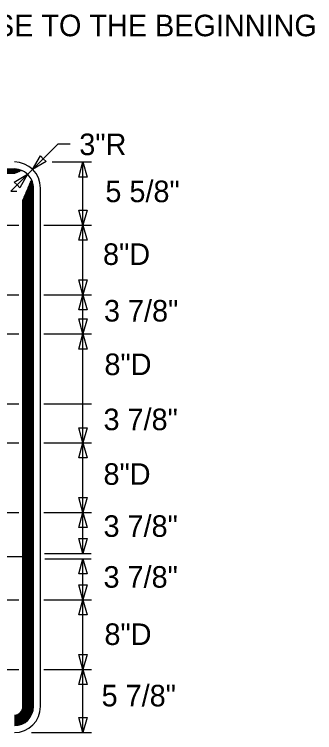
# Model space of a CAD drawing. Extents: x 15273 to 18137, y 1908 to 6555.
# Drawn here: x 17974.2 to 18091.3, y 2387.3 to 2667.1 of the extents above; entities that cross this region are included whole.
import ezdxf

# ---------------------------------------------------------------- set-up
doc = ezdxf.new("R2010")
doc.units = 0
doc.layers.add('TYPICAL_EX', color=7, linetype='Continuous')
doc.layers.add('TYPICAL_TEXT_DIMEN_PR', color=7, linetype='Continuous')

msp = doc.modelspace()

# ---------------------------------------------------------------- linework, layer by layer
at = {"layer": 'TYPICAL_EX'}
for p, q in [((17974.24, 2606.79), (17845.88, 2606.79)), ((17974.24, 2606.68), (17846.02, 2606.68)), ((17974.24, 2606.57), (17846.08, 2606.57)), ((17974.24, 2606.46), (17846.14, 2606.46)), ((17974.24, 2606.35), (17846.2, 2606.35)), ((17974.24, 2606.23), (17846.26, 2606.23)), ((17974.24, 2606.12), (17846.31, 2606.12)), ((17974.24, 2606.01), (17846.37, 2606.01)), ((17974.24, 2605.9), (17846.43, 2605.9)), ((17974.24, 2605.79), (17846.49, 2605.79)), ((17974.24, 2605.67), (17846.55, 2605.67)), ((17974.24, 2605.56), (17846.6, 2605.56)), ((17974.24, 2605.45), (17846.66, 2605.45)), ((17974.24, 2605.34), (17846.72, 2605.34)), ((17974.24, 2605.23), (17846.78, 2605.23)), ((17974.24, 2605.11), (17846.84, 2605.11)), ((17979.58, 2451.37), (17979.58, 2599.44)), ((17979.69, 2451.39), (17979.69, 2599.44)), ((17979.8, 2451.37), (17979.8, 2599.44)), ((17979.92, 2451.26), (17979.92, 2599.44)), ((17980.03, 2451.33), (17980.03, 2599.44)), ((17980.14, 2451.39), (17980.14, 2599.44)), ((17980.25, 2451.44), (17980.25, 2599.44)), ((17980.36, 2451.35), (17980.36, 2599.44)), ((17980.48, 2451.39), (17980.48, 2599.44)), ((17980.59, 2451.35), (17980.59, 2599.44)), ((17980.7, 2451.37), (17980.7, 2599.44)), ((17980.81, 2451.37), (17980.81, 2599.44)), ((17980.92, 2451.37), (17980.92, 2599.44)), ((17981.03, 2451.41), (17981.03, 2599.44)), ((17981.15, 2451.44), (17981.15, 2599.44)), ((17981.26, 2451.37), (17981.26, 2599.44)), ((17981.37, 2451.37), (17981.37, 2599.44)), ((17981.48, 2451.41), (17981.48, 2599.44)), ((17981.6, 2451.37), (17981.6, 2599.44)), ((17981.71, 2451.42), (17981.71, 2599.44)), ((17984.42, 2451.4), (17984.42, 2599.44)), ((17978.35, 2451.29), (17978.35, 2596.59)), ((17978.46, 2451.37), (17978.46, 2596.85)), ((17978.57, 2451.39), (17978.57, 2597.11)), ((17978.68, 2451.29), (17978.68, 2597.37)), ((17978.8, 2451.31), (17978.8, 2597.63)), ((17978.91, 2451.35), (17978.91, 2597.89)), ((17979.02, 2451.39), (17979.02, 2598.15)), ((17979.13, 2451.33), (17979.13, 2598.41)), ((17979.24, 2451.35), (17979.24, 2598.67)), ((17979.35, 2451.33), (17979.35, 2598.93)), ((17979.47, 2451.22), (17979.47, 2599.19)), ((17977.6, 2451.35), (17977.6, 2594.86)), ((17977.67, 2451.35), (17977.67, 2595.03)), ((17977.79, 2451.45), (17977.79, 2595.29)), ((17977.9, 2451.43), (17977.9, 2595.55)), ((17978.01, 2451.35), (17978.01, 2595.81)), ((17978.12, 2451.35), (17978.12, 2596.07)), ((17978.24, 2451.44), (17978.24, 2596.33)), ((17828.79, 2455.92), (17977.54, 2455.92)), ((17977.6, 2397.51), (17977.6, 2451.35)), ((17977.67, 2397.51), (17977.67, 2451.35)), ((17977.78, 2397.51), (17977.78, 2451.35)), ((17977.9, 2397.51), (17977.9, 2451.35)), ((17978.01, 2397.51), (17978.01, 2451.35)), ((17978.12, 2397.51), (17978.12, 2451.35)), ((17978.23, 2397.51), (17978.23, 2451.35)), ((17978.35, 2397.51), (17978.35, 2451.35)), ((17978.46, 2397.51), (17978.46, 2451.35)), ((17978.57, 2397.51), (17978.57, 2451.35)), ((17978.68, 2397.51), (17978.68, 2451.35)), ((17978.79, 2397.51), (17978.79, 2451.35)), ((17978.91, 2397.51), (17978.91, 2451.35)), ((17979.02, 2397.51), (17979.02, 2451.35)), ((17979.13, 2397.51), (17979.13, 2451.35)), ((17979.24, 2397.51), (17979.24, 2451.35)), ((17979.35, 2397.51), (17979.35, 2451.35)), ((17979.47, 2397.51), (17979.47, 2451.35)), ((17979.58, 2397.51), (17979.58, 2451.35)), ((17979.69, 2397.51), (17979.69, 2451.35)), ((17979.8, 2397.51), (17979.8, 2451.35)), ((17979.92, 2397.51), (17979.92, 2451.35)), ((17980.03, 2397.51), (17980.03, 2451.35)), ((17980.14, 2397.51), (17980.14, 2451.35)), ((17980.25, 2397.51), (17980.25, 2451.35)), ((17980.36, 2397.51), (17980.36, 2451.35)), ((17980.48, 2397.51), (17980.48, 2451.35)), ((17980.59, 2397.51), (17980.59, 2451.35)), ((17980.7, 2397.51), (17980.7, 2451.35)), ((17980.81, 2397.51), (17980.81, 2451.35)), ((17980.92, 2397.51), (17980.92, 2451.35)), ((17981.03, 2397.51), (17981.03, 2451.35)), ((17981.15, 2397.51), (17981.15, 2451.35)), ((17981.26, 2397.51), (17981.26, 2451.35)), ((17981.37, 2397.51), (17981.37, 2451.35)), ((17981.48, 2397.51), (17981.48, 2451.35)), ((17981.6, 2397.51), (17981.6, 2451.35)), ((17981.71, 2397.51), (17981.71, 2451.35)), ((17984.42, 2397.51), (17984.42, 2451.35))]:
    msp.add_line(p, q, dxfattribs=at)
for centre, radius, start, end in [((17974.24, 2599.44), 10.18, 0, 90), ((17974.24, 2599.44), 7.46, 39.0673, 90), ((17974.24, 2599.44), 7.35, 66.9087, 90), ((17974.24, 2599.44), 7.24, 67.8069, 90), ((17974.24, 2599.44), 7.13, 68.7489, 90), ((17974.24, 2599.44), 7.02, 69.7388, 90), ((17974.24, 2599.44), 6.9, 70.7811, 90), ((17974.24, 2599.44), 6.79, 71.8812, 90), ((17974.24, 2599.44), 6.68, 73.0455, 90), ((17974.24, 2599.44), 6.57, 74.2814, 90), ((17974.24, 2599.44), 6.46, 75.5979, 90), ((17974.24, 2599.44), 6.34, 77.006, 90), ((17974.24, 2599.44), 6.23, 78.5194, 90), ((17974.24, 2599.44), 6.12, 80.1555, 90), ((17974.24, 2599.44), 6.01, 81.9371, 90), ((17974.24, 2599.44), 5.9, 83.8949, 90), ((17974.24, 2599.44), 5.78, 86.0727, 90), ((17974.24, 2599.44), 5.67, 88.5362, 90), ((17974.24, 2599.44), 7.46, 0, 39.0664), ((17974.24, 2599.44), 7.02, 0, 22.4279), ((17974.24, 2599.44), 7.13, 0, 23.2988), ((17974.24, 2599.44), 7.24, 0, 24.1309), ((17974.24, 2599.44), 7.35, 0, 24.1308), ((17974.24, 2599.44), 5.34, 0, 0.1031), ((17974.24, 2599.44), 5.45, 0, 2.6891), ((17974.24, 2599.44), 5.56, 0, 4.9634), ((17974.24, 2599.44), 5.67, 0, 6.9999), ((17974.24, 2599.44), 5.78, 0, 8.847), ((17974.24, 2599.44), 5.9, 0, 10.5386), ((17974.24, 2599.44), 6.01, 0, 12.0996), ((17974.24, 2599.44), 6.12, 0, 13.5489), ((17974.24, 2599.44), 6.23, 0, 14.9011), ((17974.24, 2599.44), 6.34, 0, 16.1683), ((17974.24, 2599.44), 6.46, 0, 17.36), ((17974.24, 2599.44), 6.57, 0, 18.4842), ((17974.24, 2599.44), 6.68, 0, 19.5478), ((17974.24, 2599.44), 6.79, 0, 20.5564), ((17974.24, 2599.44), 6.9, 0, 21.5151), ((17974.24, 2397.51), 7.46, 270, 0), ((17974.24, 2397.51), 3.36, 270, 0), ((17974.24, 2397.51), 7.35, 270, 0), ((17974.24, 2397.51), 7.24, 270, 0), ((17974.24, 2397.51), 7.13, 270, 0), ((17974.24, 2397.51), 7.02, 270, 0), ((17974.24, 2397.51), 6.9, 270, 0), ((17974.24, 2397.51), 6.79, 270, 0), ((17974.24, 2397.51), 6.68, 270, 0), ((17974.24, 2397.51), 6.57, 270, 0), ((17974.24, 2397.51), 6.46, 270, 0), ((17974.24, 2397.51), 6.34, 270, 0), ((17974.24, 2397.51), 6.23, 270, 0), ((17974.24, 2397.51), 6.12, 270, 0), ((17974.24, 2397.51), 6.01, 270, 0), ((17974.24, 2397.51), 5.9, 270, 0), ((17974.24, 2397.51), 5.78, 270, 0), ((17974.24, 2397.51), 5.67, 270, 0), ((17974.24, 2397.51), 5.56, 270, 0), ((17974.24, 2397.51), 5.45, 270, 0), ((17974.24, 2397.51), 5.34, 270, 0), ((17974.24, 2397.51), 5.22, 270, 0), ((17974.24, 2397.51), 5.11, 270, 0), ((17974.24, 2397.51), 5, 270, 0), ((17974.24, 2397.51), 4.89, 270, 0), ((17974.24, 2397.51), 4.78, 270, 0), ((17974.24, 2397.51), 4.66, 270, 0), ((17974.24, 2397.51), 4.55, 270, 0), ((17974.24, 2397.51), 4.44, 270, 0), ((17974.24, 2397.51), 4.33, 270, 0), ((17974.24, 2397.51), 4.21, 270, 0), ((17974.24, 2397.51), 4.1, 270, 0), ((17974.24, 2397.51), 3.99, 270, 0), ((17974.24, 2397.51), 3.88, 270, 0), ((17974.24, 2397.51), 3.77, 270, 0), ((17974.24, 2397.51), 3.65, 270, 0), ((17974.24, 2397.51), 3.54, 270, 0), ((17974.24, 2397.51), 3.43, 270, 0), ((17974.24, 2397.51), 10.18, 270, 0)]:
    msp.add_arc(centre, radius, start, end, dxfattribs=at)
at = {"layer": 'TYPICAL_TEXT_DIMEN_PR'}
for p, q in [((17981.35, 2606.73), (17991.31, 2616.68)), ((17991.31, 2616.68), (17996.01, 2616.68)), ((17981.35, 2606.73), (17984.39, 2611.98)), ((17984.39, 2611.98), (17985.5, 2610.87)), ((17985.5, 2610.87), (17986.61, 2609.76)), ((17986.61, 2609.76), (17981.35, 2606.73)), ((17988.95, 2609.62), (18004.31, 2609.62)), ((17999.42, 2603.76), (18000.99, 2609.62)), ((18000.99, 2585.02), (18000.99, 2609.62)), ((18000.99, 2609.62), (18002.56, 2603.76)), ((17979.44, 2604.81), (17981.32, 2606.69)), ((17972.91, 2598.28), (17979.44, 2604.81)), ((17974.18, 2601.77), (17979.43, 2604.81)), ((17979.43, 2604.81), (17976.4, 2599.55)), ((18000.99, 2603.76), (17999.42, 2603.76)), ((18002.56, 2603.76), (18000.99, 2603.76)), ((17975.29, 2600.66), (17974.18, 2601.77)), ((17976.4, 2599.55), (17975.29, 2600.66)), ((17972.91, 2598.28), (17975.15, 2598.28)), ((18000.99, 2585.02), (17999.42, 2590.88)), ((17999.42, 2590.88), (18000.99, 2590.88)), ((18000.99, 2590.88), (18002.56, 2590.88)), ((18002.56, 2590.88), (18000.99, 2585.02)), ((17951.77, 2585.02), (17975.94, 2585.02)), ((17985.79, 2585.02), (18004.31, 2585.02)), ((17999.42, 2579.16), (18000.99, 2585.02)), ((18000.99, 2557.88), (18000.99, 2585.02)), ((18000.99, 2585.02), (18002.56, 2579.16)), ((18000.99, 2579.16), (17999.42, 2579.16)), ((18002.56, 2579.16), (18000.99, 2579.16)), ((18000.99, 2557.88), (17999.42, 2563.74)), ((17999.42, 2563.74), (18000.99, 2563.74)), ((18000.99, 2563.74), (18002.56, 2563.74)), ((18002.56, 2563.74), (18000.99, 2557.88)), ((17951.77, 2557.88), (17975.94, 2557.88)), ((17985.79, 2557.88), (18004.31, 2557.88)), ((17999.42, 2552.01), (18000.99, 2557.88)), ((18000.99, 2542.61), (18000.99, 2557.88)), ((18000.99, 2557.88), (18002.56, 2552.01)), ((18000.99, 2552.01), (17999.42, 2552.01)), ((18002.56, 2552.01), (18000.99, 2552.01)), ((18000.99, 2542.61), (17999.42, 2548.47)), ((17999.42, 2548.47), (18000.99, 2548.47)), ((18000.99, 2548.47), (18002.56, 2548.47)), ((18002.56, 2548.47), (18000.99, 2542.61)), ((17940.51, 2542.61), (17975.94, 2542.61)), ((17985.79, 2542.61), (18004.31, 2542.61)), ((17999.42, 2536.75), (18000.99, 2542.61)), ((18000.99, 2515.46), (18000.99, 2542.61)), ((18000.99, 2542.61), (18002.56, 2536.75)), ((18000.99, 2536.75), (17999.42, 2536.75)), ((18002.56, 2536.75), (18000.99, 2536.75)), ((17940.51, 2515.46), (17975.94, 2515.46)), ((17985.79, 2515.46), (18004.31, 2515.46)), ((18000.99, 2500.19), (18000.99, 2515.46)), ((18000.99, 2500.19), (17999.42, 2506.05)), ((17999.42, 2506.05), (18000.99, 2506.05)), ((18000.99, 2506.05), (18002.56, 2506.05)), ((18002.56, 2506.05), (18000.99, 2500.19)), ((17950.76, 2500.19), (17975.94, 2500.19)), ((17985.79, 2500.19), (18004.31, 2500.19)), ((17999.42, 2494.33), (18000.99, 2500.19)), ((18000.99, 2473.05), (18000.99, 2500.19)), ((18000.99, 2500.19), (18002.56, 2494.33)), ((18000.99, 2494.33), (17999.42, 2494.33)), ((18002.56, 2494.33), (18000.99, 2494.33)), ((18000.99, 2473.05), (17999.42, 2478.91)), ((17999.42, 2478.91), (18000.99, 2478.91)), ((18000.99, 2478.91), (18002.56, 2478.91)), ((18002.56, 2478.91), (18000.99, 2473.05)), ((17950.76, 2473.05), (17975.94, 2473.05)), ((17985.79, 2473.05), (18004.31, 2473.05)), ((17999.42, 2467.18), (18000.99, 2473.05)), ((18000.99, 2457.07), (18000.99, 2473.05)), ((18000.99, 2473.05), (18000.99, 2473.05)), ((18000.99, 2473.05), (18000.99, 2473.04)), ((18000.99, 2473.05), (18002.56, 2467.18)), ((18000.99, 2467.18), (17999.42, 2467.18)), ((18002.56, 2467.18), (18000.99, 2467.18)), ((18000.99, 2457.07), (17999.42, 2462.93)), ((17999.42, 2462.93), (18000.99, 2462.93)), ((18000.99, 2462.93), (18002.56, 2462.93)), ((18002.56, 2462.93), (18000.99, 2457.07)), ((17986.04, 2457.07), (18004.22, 2457.07)), ((17986.13, 2455.06), (18004.13, 2455.06)), ((17999.42, 2449.19), (18000.99, 2455.05)), ((18000.99, 2439.07), (18000.99, 2455.05)), ((18000.99, 2455.05), (18002.56, 2449.19)), ((18002.2, 2451.35), (18002.21, 2451.34)), ((18000.99, 2449.19), (17999.42, 2449.19)), ((18002.56, 2449.19), (18000.99, 2449.19)), ((18000.99, 2439.07), (17999.42, 2444.94)), ((17999.42, 2444.94), (18000.99, 2444.94)), ((18000.99, 2444.94), (18002.56, 2444.94)), ((18002.56, 2444.94), (18000.99, 2439.07)), ((17956.07, 2439.07), (17975.94, 2439.07)), ((17985.79, 2439.07), (18004.31, 2439.07)), ((17999.42, 2433.21), (18000.99, 2439.07)), ((18000.99, 2411.93), (18000.99, 2439.07)), ((18000.99, 2439.07), (18002.56, 2433.21)), ((18000.99, 2433.21), (17999.42, 2433.21)), ((18002.56, 2433.21), (18000.99, 2433.21)), ((18000.99, 2411.93), (17999.42, 2417.79)), ((17999.42, 2417.79), (18000.99, 2417.79)), ((18000.99, 2417.79), (18002.56, 2417.79)), ((18002.56, 2417.79), (18000.99, 2411.93)), ((17948.66, 2411.93), (17975.94, 2411.93)), ((17985.79, 2411.93), (18004.31, 2411.93)), ((17999.42, 2406.07), (18000.99, 2411.93)), ((18000.99, 2387.33), (18000.99, 2411.93)), ((18000.99, 2411.93), (18002.56, 2406.07)), ((18000.99, 2406.07), (17999.42, 2406.07)), ((18002.56, 2406.07), (18000.99, 2406.07)), ((18000.99, 2387.33), (17999.42, 2393.19)), ((17999.42, 2393.19), (18000.99, 2393.19)), ((18000.99, 2393.19), (18002.56, 2393.19)), ((18002.56, 2393.19), (18000.99, 2387.33)), ((17980.93, 2387.33), (18004.31, 2387.33))]:
    msp.add_line(p, q, dxfattribs=at)

# ---------------------------------------------------------------- texts
for s, p in [('LIMITATIONS RESTRICT ITS PLACEMENT AS INDICATED, THEN IT SHALL BE PLACED AS CLOSE TO THE BEGINNING', (17463.6, 2658.59)), ('3"R', (17999.56, 2612.28)), ('5 5/8"', (18009.72, 2593.96)), ('8"D', (18008.81, 2569.51)), ('3 7/8"', (18009.17, 2547.46)), ('8"D', (18009.35, 2526.6)), ('3 7/8"', (18008.99, 2505.14)), ('8"D', (18008.99, 2483.86)), ('3 7/8"', (18008.99, 2463.59)), ('3 7/8"', (18008.99, 2443.78)), ('8"D', (18009.35, 2421.47)), ('5 7/8"', (18008.25, 2397.55))]:
    msp.add_text(s, height=8.4, dxfattribs=at).set_placement(p)

doc.saveas('drawing.dxf')
